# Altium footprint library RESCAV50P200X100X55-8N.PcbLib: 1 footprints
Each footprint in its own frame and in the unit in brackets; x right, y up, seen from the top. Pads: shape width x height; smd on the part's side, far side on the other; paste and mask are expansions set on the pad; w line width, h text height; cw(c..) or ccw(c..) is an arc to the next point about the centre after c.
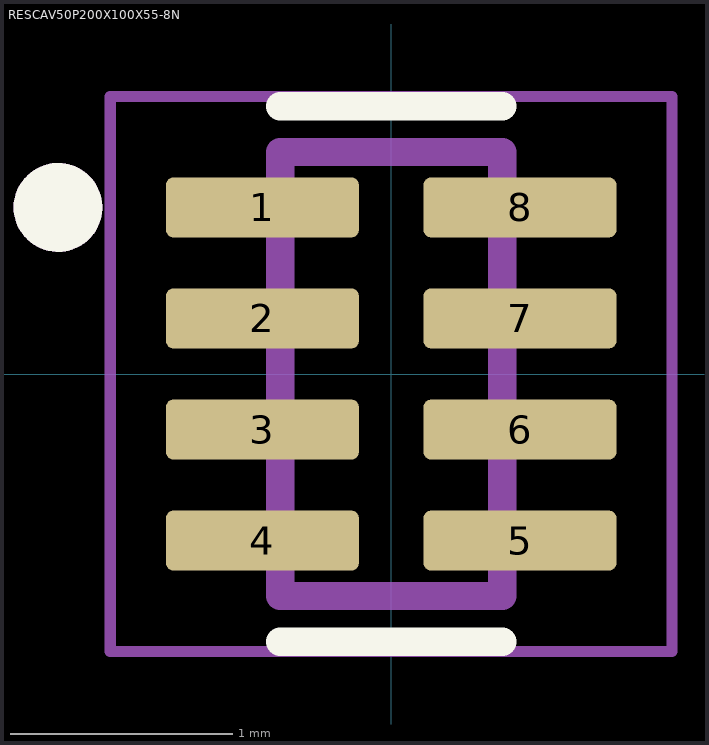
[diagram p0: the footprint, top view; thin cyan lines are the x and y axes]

## RESCAV50P200X100X55-8N [mm]
pads (8):
  rrect25% 0.87x0.27 smd: 1(-0.58,0.75) 2(-0.58,0.25) 3(-0.58,-0.25) 4(-0.58,-0.75) 5(0.58,-0.75) 6(0.58,-0.25) 7(0.58,0.25) 8(0.58,0.75)
Top Overlay:
  circle w0.2: c-1.5,0.75 r0.1
  lines w0.127: -0.5,-1.205 0.5,-1.205 ; -0.5,1.205 0.5,1.205
Mechanical 13:
  circle w0.2: c-1.5,0.75 r0.1
  lines w0.127: -0.5,-1 0.5,-1 0.5,1 -0.5,1 -0.5,-1
Mechanical 15:
  lines w0.05: -1.265,-1.25 1.265,-1.25 1.265,1.25 -1.265,1.25 -1.265,-1.25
